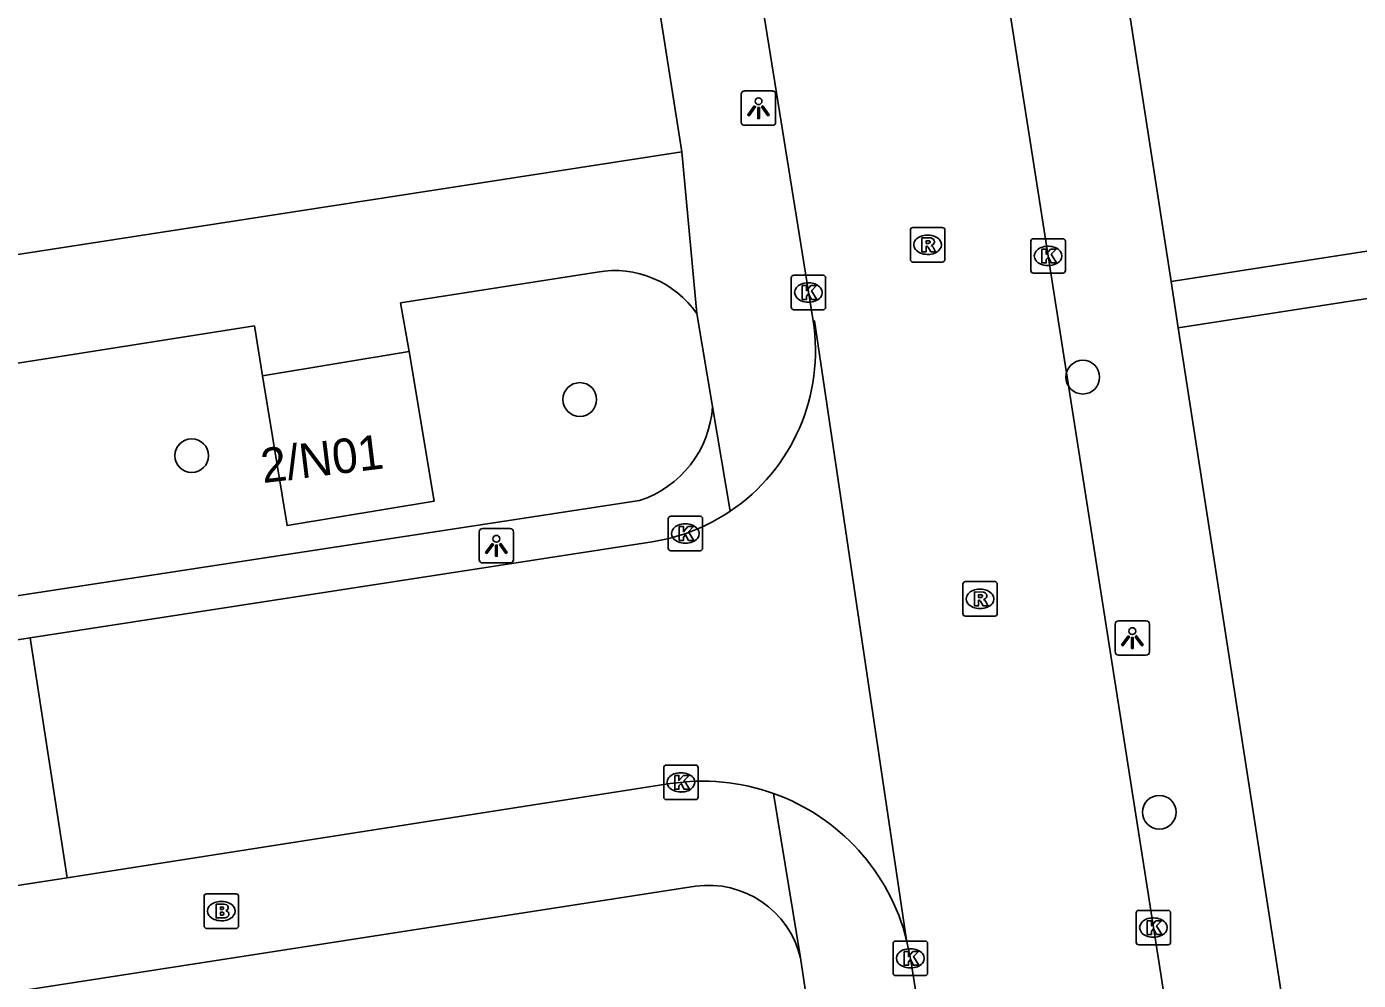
# Model space of a CAD drawing. Extents: x 160077 to 160945, y 386481 to 387498.
# Drawn here: x 160325.76 to 160364.4, y 387353.43 to 387381.1 of the extents above; entities that cross this region are included whole.
import ezdxf

# ---------------------------------------------------------------- set-up
doc = ezdxf.new("R2010")
doc.units = 0
for name, color, linetype in [('IMGEO_Boom', 7, 'Continuous'), ('IMGEO_Brandkraan', 7, 'Continuous'), ('IMGEO_Kolk', 7, 'Continuous'), ('IMGEO_Lichtpunt', 7, 'Continuous'), ('IMGEO_Pand', 7, 'Continuous'), ('IMGEO_Pand_nummerreeks', 7, 'Continuous'), ('IMGEO_Rijbaan_lokaal_open', 7, 'Continuous'), ('IMGEO_Rioolput', 7, 'Continuous'), ('IMGEO_Voetpad_open', 7, 'Continuous')]:
    doc.layers.add(name, color=color, linetype=linetype)

msp = doc.modelspace()

# ---------------------------------------------------------------- linework, layer by layer
at = {"layer": 'IMGEO_Boom'}
for centre in [(160356.404, 387370.927), (160341.811, 387370.278), (160330.552, 387368.649), (160358.624, 387358.305)]:
    msp.add_circle(centre, 0.489, dxfattribs=at)
at = {"layer": 'IMGEO_Brandkraan'}
for p, q in [((160330.91, 387355.011), (160330.91, 387355.863)), ((160330.985, 387355.937), (160331.837, 387355.937)), ((160331.398, 387355.717), (160331.423, 387355.717)), ((160331.911, 387355.863), (160331.911, 387355.011)), ((160331.837, 387354.937), (160330.985, 387354.937)), ((160331.421, 387355.157), (160331.396, 387355.157))]:
    msp.add_line(p, q, dxfattribs=at)
for points in [[(160330.91, 387355.011), (160330.91, 387355.863)], [(160330.985, 387355.937), (160331.837, 387355.937)], [(160331.258, 387355.637), (160331.258, 387355.237), (160331.471, 387355.237)], [(160331.489, 387355.637), (160331.258, 387355.637)], [(160331.911, 387355.863), (160331.911, 387355.011)], [(160331.437, 387355.556), (160331.383, 387355.556), (160331.383, 387355.48)], [(160331.383, 387355.48), (160331.436, 387355.48)], [(160331.445, 387355.404), (160331.383, 387355.404), (160331.383, 387355.323)], [(160331.383, 387355.323), (160331.445, 387355.323)], [(160331.837, 387354.937), (160330.985, 387354.937)]]:
    msp.add_lwpolyline(points, dxfattribs=at)
for centre, radius, start, end in [((160330.987, 387355.861), 0.0765, 91.552, 178.448), ((160330.987, 387355.861), 0.0765, 91.552, 178.448), ((160331.493, 387355.492), 0.145, 59.4692, 91.5367), ((160331.835, 387355.861), 0.0765, 1.552, 88.448), ((160331.835, 387355.861), 0.0765, 1.552, 88.448), ((160331.438, 387355.518), 0.0379, 267.8285, 90.9355), ((160331.446, 387355.363), 0.0404, 269.8759, 90.5077), ((160331.477, 387355.488), 0.251, 268.6676, 293.5347), ((160331.518, 387355.539), 0.0922, 285.5137, 58.1501), ((160331.523, 387355.347), 0.105, 301.3115, 78.989), ((160330.987, 387355.013), 0.0765, 181.552, 268.448), ((160330.987, 387355.013), 0.0765, 181.552, 268.448), ((160331.835, 387355.013), 0.0765, 271.552, 358.448), ((160331.835, 387355.013), 0.0765, 271.552, 358.448)]:
    msp.add_arc(centre, radius, start, end, dxfattribs=at)
for centre, major_axis, ratio, start_param, end_param in [((160331.397, 387355.437), (-0.387, 0.002), 0.722429, 4.712389, 7.853982), ((160331.422, 387355.437), (-0.39, 0.002), 0.717154, 1.570796, 4.712389)]:
    msp.add_ellipse(centre, major_axis=major_axis, ratio=ratio, start_param=start_param, end_param=end_param, dxfattribs=at)
at = {"layer": 'IMGEO_Kolk'}
for p, q in [((160354.898, 387374.017), (160354.898, 387374.869)), ((160354.973, 387374.943), (160355.825, 387374.943)), ((160355.386, 387374.723), (160355.411, 387374.723)), ((160355.899, 387374.869), (160355.899, 387374.017)), ((160347.943, 387372.956), (160347.943, 387373.808)), ((160348.018, 387373.882), (160348.87, 387373.882)), ((160348.944, 387373.808), (160348.944, 387372.956)), ((160355.825, 387373.943), (160354.973, 387373.943)), ((160355.409, 387374.163), (160355.384, 387374.163)), ((160348.431, 387373.662), (160348.456, 387373.662)), ((160348.454, 387373.102), (160348.429, 387373.102)), ((160348.87, 387372.882), (160348.018, 387372.882)), ((160344.448, 387366.891), (160345.3, 387366.891)), ((160344.373, 387365.965), (160344.373, 387366.817)), ((160344.861, 387366.671), (160344.886, 387366.671)), ((160345.374, 387366.817), (160345.374, 387365.965)), ((160344.884, 387366.111), (160344.859, 387366.111)), ((160345.3, 387365.891), (160344.448, 387365.891)), ((160344.245, 387358.746), (160344.245, 387359.598)), ((160344.32, 387359.672), (160345.172, 387359.672)), ((160345.246, 387359.598), (160345.246, 387358.746)), ((160344.733, 387359.452), (160344.758, 387359.452)), ((160344.756, 387358.892), (160344.731, 387358.892)), ((160345.172, 387358.672), (160344.32, 387358.672)), ((160357.952, 387354.533), (160357.952, 387355.385)), ((160358.027, 387355.459), (160358.879, 387355.459)), ((160358.953, 387355.385), (160358.953, 387354.533)), ((160358.44, 387355.239), (160358.465, 387355.239)), ((160350.9, 387353.641), (160350.9, 387354.493)), ((160350.975, 387354.567), (160351.827, 387354.567)), ((160351.901, 387354.493), (160351.901, 387353.641)), ((160358.463, 387354.679), (160358.438, 387354.679)), ((160351.388, 387354.347), (160351.413, 387354.347)), ((160358.879, 387354.459), (160358.027, 387354.459)), ((160351.411, 387353.787), (160351.386, 387353.787)), ((160351.827, 387353.567), (160350.975, 387353.567))]:
    msp.add_line(p, q, dxfattribs=at)
for points in [[(160354.898, 387374.017), (160354.898, 387374.869)], [(160354.973, 387374.943), (160355.825, 387374.943)], [(160355.219, 387374.643), (160355.342, 387374.643), (160355.342, 387374.492), (160355.472, 387374.643), (160355.636, 387374.643), (160355.49, 387374.492), (160355.643, 387374.243), (160355.491, 387374.243), (160355.406, 387374.407), (160355.342, 387374.34), (160355.342, 387374.243), (160355.219, 387374.243), (160355.219, 387374.643)], [(160355.899, 387374.869), (160355.899, 387374.017)], [(160347.943, 387372.956), (160347.943, 387373.808)], [(160348.018, 387373.882), (160348.87, 387373.882)], [(160348.944, 387373.808), (160348.944, 387372.956)], [(160355.825, 387373.943), (160354.973, 387373.943)], [(160348.264, 387373.582), (160348.387, 387373.582), (160348.387, 387373.431), (160348.517, 387373.582), (160348.681, 387373.582), (160348.535, 387373.431), (160348.688, 387373.182), (160348.536, 387373.182), (160348.451, 387373.346), (160348.387, 387373.279), (160348.387, 387373.182), (160348.264, 387373.182), (160348.264, 387373.582)], [(160348.87, 387372.882), (160348.018, 387372.882)], [(160344.448, 387366.891), (160345.3, 387366.891)], [(160344.373, 387365.965), (160344.373, 387366.817)], [(160344.694, 387366.591), (160344.817, 387366.591), (160344.817, 387366.44), (160344.947, 387366.591), (160345.111, 387366.591), (160344.965, 387366.44), (160345.118, 387366.191), (160344.966, 387366.191), (160344.881, 387366.355), (160344.817, 387366.288), (160344.817, 387366.191), (160344.694, 387366.191), (160344.694, 387366.591)], [(160345.374, 387366.817), (160345.374, 387365.965)], [(160345.3, 387365.891), (160344.448, 387365.891)], [(160344.245, 387358.746), (160344.245, 387359.598)], [(160344.32, 387359.672), (160345.172, 387359.672)], [(160345.246, 387359.598), (160345.246, 387358.746)], [(160344.566, 387359.372), (160344.689, 387359.372), (160344.689, 387359.221), (160344.819, 387359.372), (160344.983, 387359.372), (160344.837, 387359.221), (160344.99, 387358.972), (160344.838, 387358.972), (160344.753, 387359.136), (160344.689, 387359.069), (160344.689, 387358.972), (160344.566, 387358.972), (160344.566, 387359.372)], [(160345.172, 387358.672), (160344.32, 387358.672)], [(160357.952, 387354.533), (160357.952, 387355.385)], [(160358.027, 387355.459), (160358.879, 387355.459)], [(160358.953, 387355.385), (160358.953, 387354.533)], [(160358.273, 387355.159), (160358.396, 387355.159), (160358.396, 387355.008), (160358.526, 387355.159), (160358.69, 387355.159), (160358.544, 387355.008), (160358.697, 387354.759), (160358.545, 387354.759), (160358.46, 387354.923), (160358.396, 387354.856), (160358.396, 387354.759), (160358.273, 387354.759), (160358.273, 387355.159)], [(160350.9, 387353.641), (160350.9, 387354.493)], [(160350.975, 387354.567), (160351.827, 387354.567)], [(160351.901, 387354.493), (160351.901, 387353.641)], [(160351.221, 387354.267), (160351.344, 387354.267), (160351.344, 387354.116), (160351.474, 387354.267), (160351.638, 387354.267), (160351.492, 387354.116), (160351.645, 387353.867), (160351.493, 387353.867), (160351.408, 387354.031), (160351.344, 387353.964), (160351.344, 387353.867), (160351.221, 387353.867), (160351.221, 387354.267)], [(160358.879, 387354.459), (160358.027, 387354.459)], [(160351.827, 387353.567), (160350.975, 387353.567)]]:
    msp.add_lwpolyline(points, dxfattribs=at)
for centre, start, end in [((160354.975, 387374.867), 91.552, 178.448), ((160354.975, 387374.867), 91.552, 178.448), ((160355.823, 387374.867), 1.552, 88.448), ((160355.823, 387374.867), 1.552, 88.448), ((160348.02, 387373.806), 91.552, 178.448), ((160348.02, 387373.806), 91.552, 178.448), ((160348.868, 387373.806), 1.552, 88.448), ((160348.868, 387373.806), 1.552, 88.448), ((160354.975, 387374.019), 181.552, 268.448), ((160354.975, 387374.019), 181.552, 268.448), ((160355.823, 387374.019), 271.552, 358.448), ((160355.823, 387374.019), 271.552, 358.448), ((160348.02, 387372.958), 181.552, 268.448), ((160348.02, 387372.958), 181.552, 268.448), ((160348.868, 387372.958), 271.552, 358.448), ((160348.868, 387372.958), 271.552, 358.448), ((160344.45, 387366.815), 91.552, 178.448), ((160344.45, 387366.815), 91.552, 178.448), ((160345.298, 387366.815), 1.552, 88.448), ((160345.298, 387366.815), 1.552, 88.448), ((160344.45, 387365.967), 181.552, 268.448), ((160344.45, 387365.967), 181.552, 268.448), ((160345.298, 387365.967), 271.552, 358.448), ((160345.298, 387365.967), 271.552, 358.448), ((160344.322, 387359.596), 91.552, 178.448), ((160344.322, 387359.596), 91.552, 178.448), ((160345.17, 387359.596), 1.552, 88.448), ((160345.17, 387359.596), 1.552, 88.448), ((160344.322, 387358.748), 181.552, 268.448), ((160344.322, 387358.748), 181.552, 268.448), ((160345.17, 387358.748), 271.552, 358.448), ((160345.17, 387358.748), 271.552, 358.448), ((160358.029, 387355.383), 91.552, 178.448), ((160358.029, 387355.383), 91.552, 178.448), ((160358.877, 387355.383), 1.552, 88.448), ((160358.877, 387355.383), 1.552, 88.448), ((160350.977, 387354.491), 91.552, 178.448), ((160350.977, 387354.491), 91.552, 178.448), ((160351.825, 387354.491), 1.552, 88.448), ((160351.825, 387354.491), 1.552, 88.448), ((160358.029, 387354.535), 181.552, 268.448), ((160358.029, 387354.535), 181.552, 268.448), ((160358.877, 387354.535), 271.552, 358.448), ((160358.877, 387354.535), 271.552, 358.448), ((160350.977, 387353.643), 181.552, 268.448), ((160350.977, 387353.643), 181.552, 268.448), ((160351.825, 387353.643), 271.552, 358.448), ((160351.825, 387353.643), 271.552, 358.448)]:
    msp.add_arc(centre, 0.0765, start, end, dxfattribs=at)
for centre, major_axis, ratio, start_param, end_param in [((160355.385, 387374.443), (-0.387, 0.002), 0.722429, 4.712389, 7.853982), ((160355.41, 387374.443), (-0.39, 0.002), 0.717154, 1.570796, 4.712389), ((160348.43, 387373.382), (-0.387, 0.002), 0.722429, 4.712389, 7.853982), ((160348.455, 387373.382), (-0.39, 0.002), 0.717154, 1.570796, 4.712389), ((160344.86, 387366.391), (-0.387, 0.002), 0.722429, 4.712389, 7.853982), ((160344.885, 387366.391), (-0.39, 0.002), 0.717154, 1.570796, 4.712389), ((160344.732, 387359.172), (-0.387, 0.002), 0.722429, 4.712389, 7.853982), ((160344.757, 387359.172), (-0.39, 0.002), 0.717154, 1.570796, 4.712389), ((160358.439, 387354.959), (-0.387, 0.002), 0.722429, 4.712389, 7.853982), ((160358.464, 387354.959), (-0.39, 0.002), 0.717154, 1.570796, 4.712389), ((160351.387, 387354.067), (-0.387, 0.002), 0.722429, 4.712389, 7.853982), ((160351.412, 387354.067), (-0.39, 0.002), 0.717154, 1.570796, 4.712389)]:
    msp.add_ellipse(centre, major_axis=major_axis, ratio=ratio, start_param=start_param, end_param=end_param, dxfattribs=at)
at = {"layer": 'IMGEO_Lichtpunt'}
for p, q in [((160347.399, 387379.228), (160346.591, 387379.228)), ((160347.399, 387379.228), (160346.591, 387379.228)), ((160346.497, 387379.133), (160346.497, 387378.326)), ((160346.497, 387379.133), (160346.497, 387378.326)), ((160347.493, 387378.326), (160347.493, 387379.133)), ((160347.493, 387378.326), (160347.493, 387379.133)), ((160346.591, 387378.232), (160347.399, 387378.232)), ((160346.591, 387378.232), (160347.399, 387378.232)), ((160339.794, 387366.534), (160338.986, 387366.534)), ((160339.794, 387366.534), (160338.986, 387366.534)), ((160338.892, 387366.439), (160338.892, 387365.632)), ((160338.892, 387366.439), (160338.892, 387365.632)), ((160339.888, 387365.632), (160339.888, 387366.439)), ((160339.888, 387365.632), (160339.888, 387366.439)), ((160338.986, 387365.538), (160339.794, 387365.538)), ((160338.986, 387365.538), (160339.794, 387365.538)), ((160357.342, 387363.762), (160357.342, 387362.955)), ((160357.342, 387363.762), (160357.342, 387362.955)), ((160358.244, 387363.857), (160357.436, 387363.857)), ((160358.244, 387363.857), (160357.436, 387363.857)), ((160358.338, 387362.955), (160358.338, 387363.762)), ((160358.338, 387362.955), (160358.338, 387363.762)), ((160357.436, 387362.861), (160358.244, 387362.861)), ((160357.436, 387362.861), (160358.244, 387362.861))]:
    msp.add_line(p, q, dxfattribs=at)
for points in [[(160346.871, 387378.797), (160346.91, 387378.769), (160346.722, 387378.507), (160346.684, 387378.534), (160346.871, 387378.797)], [(160346.973, 387378.749), (160347.02, 387378.749), (160347.02, 387378.427), (160346.973, 387378.427), (160346.973, 387378.749)], [(160347.083, 387378.769), (160347.121, 387378.796), (160347.308, 387378.534), (160347.269, 387378.506), (160347.083, 387378.769)], [(160339.266, 387366.103), (160339.305, 387366.075), (160339.117, 387365.813), (160339.079, 387365.84), (160339.266, 387366.103)], [(160339.478, 387366.075), (160339.516, 387366.102), (160339.703, 387365.84), (160339.664, 387365.812), (160339.478, 387366.075)], [(160339.368, 387366.055), (160339.415, 387366.055), (160339.415, 387365.733), (160339.368, 387365.733), (160339.368, 387366.055)], [(160357.716, 387363.426), (160357.755, 387363.398), (160357.567, 387363.136), (160357.529, 387363.163), (160357.716, 387363.426)], [(160357.818, 387363.378), (160357.865, 387363.378), (160357.865, 387363.056), (160357.818, 387363.056), (160357.818, 387363.378)], [(160357.928, 387363.398), (160357.966, 387363.425), (160358.153, 387363.163), (160358.114, 387363.135), (160357.928, 387363.398)]]:
    msp.add_lwpolyline(points, dxfattribs=at)
for centre in [(160346.996, 387378.931), (160339.391, 387366.237), (160357.841, 387363.56)]:
    msp.add_circle(centre, 0.0994, dxfattribs=at)
for centre, start, end in [((160346.591, 387379.133), 90, 180), ((160346.591, 387379.133), 90, 180), ((160347.399, 387379.133), 0, 90), ((160347.399, 387379.133), 0, 90), ((160346.591, 387378.326), 180, 270), ((160346.591, 387378.326), 180, 270), ((160347.399, 387378.326), 270, 0), ((160347.399, 387378.326), 270, 360), ((160338.986, 387366.439), 90, 180), ((160338.986, 387366.439), 90, 180), ((160339.794, 387366.439), 0, 90), ((160339.794, 387366.439), 0, 90), ((160338.986, 387365.632), 180, 270), ((160338.986, 387365.632), 180, 270), ((160339.794, 387365.632), 270, 0), ((160339.794, 387365.632), 270, 360), ((160357.436, 387363.762), 90, 180), ((160357.436, 387363.762), 90, 180), ((160358.244, 387363.762), 0, 90), ((160358.244, 387363.762), 0, 90), ((160357.436, 387362.955), 180, 270), ((160357.436, 387362.955), 180, 270), ((160358.244, 387362.955), 270, 0), ((160358.244, 387362.955), 270, 360)]:
    msp.add_arc(centre, 0.0946, start, end, dxfattribs=at)
at = {"layer": 'IMGEO_Pand'}
for points in [[(160332.601, 387370.967), (160336.863, 387371.671)], [(160336.863, 387371.671), (160337.581, 387367.327), (160333.319, 387366.623), (160332.601, 387370.967)]]:
    msp.add_lwpolyline(points, dxfattribs=at)
at = {"layer": 'IMGEO_Rijbaan_lokaal_open'}
for points in [[(160348.577, 387372.565), (160343.75, 387402.638)], [(160352.799, 387391.033), (160358.665, 387353.61), (160366.562, 387302.662), (160369.173, 387285.284)], [(160351.293, 387354.598), (160348.617, 387372.556), (160348.577, 387372.565)], [(160343.908, 387366.152), (160325.861, 387363.367)], [(160323.094, 387362.939), (160325.861, 387363.367)], [(160325.861, 387363.367), (160326.936, 387356.404)], [(160326.936, 387356.404), (160344.432, 387359.134)], [(160326.936, 387356.404), (160324.17, 387355.972)], [(160357.73, 387313.614), (160353.738, 387339.43), (160353.156, 387343.079), (160351.403, 387354.063), (160351.293, 387354.598)]]:
    msp.add_lwpolyline(points, dxfattribs=at)
for centre, radius, start, end in [((160343.056, 387371.678), 5.592, 303.867, 9.1245), ((160343.06, 387371.671), 5.584, 278.7391, 303.8743), ((160345.372, 387353.078), 6.129, 70.3347, 98.8188), ((160345.37, 387353.098), 6.11, 14.2104, 70.2551)]:
    msp.add_arc(centre, radius, start, end, dxfattribs=at)
at = {"layer": 'IMGEO_Rioolput'}
for p, q in [((160351.402, 387374.341), (160351.402, 387375.193)), ((160351.477, 387375.267), (160352.329, 387375.267)), ((160351.89, 387375.047), (160351.915, 387375.047)), ((160352.403, 387375.193), (160352.403, 387374.341)), ((160352.329, 387374.267), (160351.477, 387374.267)), ((160351.913, 387374.487), (160351.888, 387374.487)), ((160352.922, 387364.069), (160352.922, 387364.921)), ((160352.997, 387364.995), (160353.849, 387364.995)), ((160353.923, 387364.921), (160353.923, 387364.069)), ((160353.41, 387364.775), (160353.435, 387364.775)), ((160353.433, 387364.215), (160353.408, 387364.215)), ((160353.849, 387363.995), (160352.997, 387363.995))]:
    msp.add_line(p, q, dxfattribs=at)
for points in [[(160351.402, 387374.341), (160351.402, 387375.193)], [(160351.477, 387375.267), (160352.329, 387375.267)], [(160351.991, 387374.965), (160351.739, 387374.967), (160351.739, 387374.567)], [(160352.403, 387375.193), (160352.403, 387374.341)], [(160351.739, 387374.567), (160351.863, 387374.567), (160351.863, 387374.729), (160351.874, 387374.729)], [(160351.917, 387374.886), (160351.863, 387374.886), (160351.863, 387374.805)], [(160351.863, 387374.805), (160351.915, 387374.805)], [(160351.921, 387374.7), (160351.992, 387374.567), (160352.132, 387374.567), (160352.067, 387374.693)], [(160352.329, 387374.267), (160351.477, 387374.267)], [(160352.922, 387364.069), (160352.922, 387364.921)], [(160352.997, 387364.995), (160353.849, 387364.995)], [(160353.923, 387364.921), (160353.923, 387364.069)], [(160353.511, 387364.693), (160353.259, 387364.695), (160353.259, 387364.295)], [(160353.437, 387364.614), (160353.383, 387364.614), (160353.383, 387364.533)], [(160353.383, 387364.533), (160353.435, 387364.533)], [(160353.259, 387364.295), (160353.383, 387364.295), (160353.383, 387364.457), (160353.394, 387364.457)], [(160353.441, 387364.428), (160353.512, 387364.295), (160353.652, 387364.295), (160353.587, 387364.421)], [(160353.849, 387363.995), (160352.997, 387363.995)]]:
    msp.add_lwpolyline(points, dxfattribs=at)
for centre, radius, start, end in [((160351.479, 387375.191), 0.0765, 91.552, 178.448), ((160351.479, 387375.191), 0.0765, 91.552, 178.448), ((160351.99, 387374.855), 0.109, 350.3612, 89.416), ((160352.327, 387375.191), 0.0765, 1.552, 88.448), ((160352.327, 387375.191), 0.0765, 1.552, 88.448), ((160351.873, 387374.676), 0.0533, 26.0293, 88.6989), ((160351.899, 387374.994), 0.19, 274.7715, 282.9687), ((160351.923, 387374.79), 0.0964, 77.0061, 93.1865), ((160351.937, 387374.847), 0.0378, 276.6634, 79.6772), ((160351.988, 387374.855), 0.112, 277.5842, 350.9817), ((160351.972, 387374.64), 0.108, 29.5134, 73.7905), ((160351.479, 387374.343), 0.0765, 181.552, 268.448), ((160351.479, 387374.343), 0.0765, 181.552, 268.448), ((160352.327, 387374.343), 0.0765, 271.552, 358.448), ((160352.327, 387374.343), 0.0765, 271.552, 358.448), ((160352.999, 387364.919), 0.0765, 91.552, 178.448), ((160352.999, 387364.919), 0.0765, 91.552, 178.448), ((160353.847, 387364.919), 0.0765, 1.552, 88.448), ((160353.847, 387364.919), 0.0765, 1.552, 88.448), ((160353.419, 387364.722), 0.19, 274.7715, 282.9687), ((160353.443, 387364.518), 0.0964, 77.0061, 93.1865), ((160353.457, 387364.575), 0.0378, 276.6634, 79.6772), ((160353.51, 387364.583), 0.109, 350.3612, 89.416), ((160353.508, 387364.583), 0.112, 277.5842, 350.9817), ((160353.393, 387364.404), 0.0533, 26.0293, 88.6989), ((160353.492, 387364.368), 0.108, 29.5134, 73.7905), ((160352.999, 387364.071), 0.0765, 181.552, 268.448), ((160352.999, 387364.071), 0.0765, 181.552, 268.448), ((160353.847, 387364.071), 0.0765, 271.552, 358.448), ((160353.847, 387364.071), 0.0765, 271.552, 358.448)]:
    msp.add_arc(centre, radius, start, end, dxfattribs=at)
for centre, major_axis, ratio, start_param, end_param in [((160351.889, 387374.767), (-0.387, 0.002), 0.722429, 4.712389, 7.853982), ((160351.914, 387374.767), (-0.39, 0.002), 0.717154, 1.570796, 4.712389), ((160353.409, 387364.495), (-0.387, 0.002), 0.722429, 4.712389, 7.853982), ((160353.434, 387364.495), (-0.39, 0.002), 0.717154, 1.570796, 4.712389)]:
    msp.add_ellipse(centre, major_axis=major_axis, ratio=ratio, start_param=start_param, end_param=end_param, dxfattribs=at)
at = {"layer": 'IMGEO_Voetpad_open'}
for points in [[(160339.073, 387413.649), (160344.769, 387377.466)], [(160358.965, 387373.701), (160356.137, 387391.954)], [(160393.162, 387373.819), (160392.576, 387377.77), (160393.076, 387377.848), (160392.9, 387378.959), (160392.607, 387378.914), (160358.965, 387373.701)], [(160344.769, 387377.466), (160321.622, 387373.883)], [(160344.769, 387377.466), (160345.211, 387372.769)], [(160382.955, 387376.039), (160359.174, 387372.354)], [(160336.863, 387371.671), (160336.612, 387373.08), (160342.314, 387373.977)], [(160359.174, 387372.354), (160358.965, 387373.701)], [(160345.211, 387372.769), (160345.664, 387370.074)], [(160322.124, 387370.799), (160332.373, 387372.412), (160332.601, 387370.967)], [(160372.658, 387285.339), (160359.174, 387372.354)], [(160345.664, 387370.074), (160346.172, 387367.035)], [(160343.545, 387367.349), (160323.128, 387364.228)], [(160347.434, 387358.849), (160348.215, 387354.083)], [(160277.066, 387345.597), (160345.165, 387356.158)], [(160348.215, 387354.083), (160351.371, 387332.958)]]:
    msp.add_lwpolyline(points, dxfattribs=at)
for centre, radius, start, end in [((160342.81, 387371.088), 2.931, 34.9926, 99.7367), ((160342.585, 387370.282), 3.086, 288.1218, 356.1398), ((160345.543, 387353.434), 2.75, 13.6449, 97.898)]:
    msp.add_arc(centre, radius, start, end, dxfattribs=at)

# ---------------------------------------------------------------- texts
at = {"layer": 'IMGEO_Pand_nummerreeks'}
msp.add_text('2/N01', height=1, rotation=6.953, dxfattribs=at).set_placement((160332.619, 387367.852))

doc.saveas('drawing.dxf')
